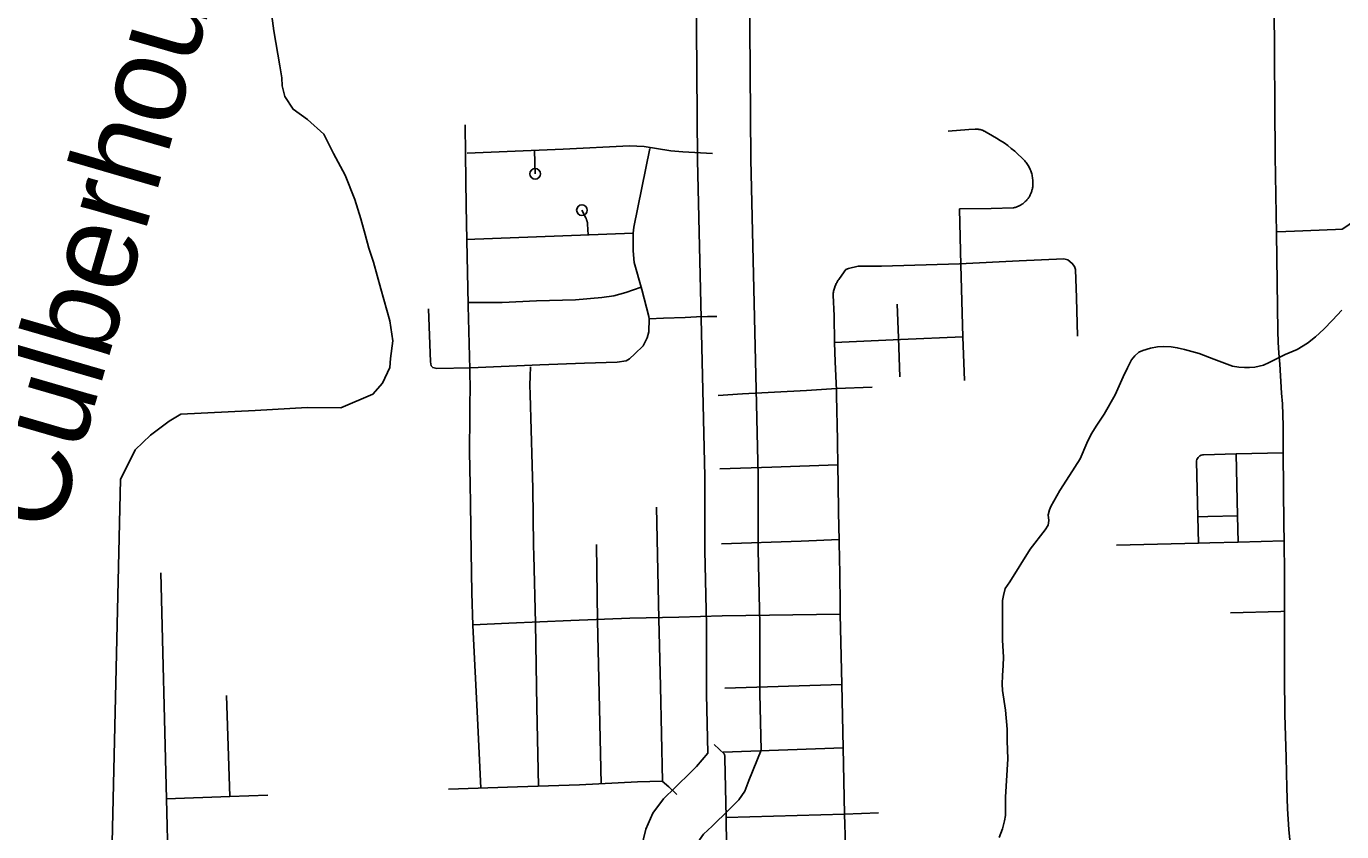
# Model space of a CAD drawing. Extents: x 309348 to 309445, y 336383 to 336484.
# Drawn here: x 309348.279 to 309349.513, y 336400.809 to 336401.564 of the extents above; entities that cross this region are included whole.
import ezdxf

# ---------------------------------------------------------------- set-up
doc = ezdxf.new("R2010")
doc.units = 0
doc.layers.add('R_Annotation', color=7, linetype='Continuous')

msp = doc.modelspace()

# ---------------------------------------------------------------- linework, layer by layer
at = {"layer": 'R_Annotation'}
for points in [[(309348.9004, 336402.0724), (309348.9007, 336402.03), (309348.9072, 336401.6455), (309348.9086, 336401.4386), (309348.9156, 336401.1419), (309348.9156, 336401.0724), (309348.9171, 336401.0028), (309348.9171, 336400.9377), (309348.9184, 336400.8825)], [(309348.9683, 336400.8852), (309348.9671, 336400.9383), (309348.9672, 336401.0034), (309348.9656, 336401.073), (309348.9656, 336401.1425), (309348.9586, 336401.4393), (309348.9572, 336401.6461), (309348.9507, 336402.0306), (309348.9504, 336402.0727)], [(309349.4519, 336401.3699), (309349.4507, 336401.4424), (309349.4496, 336401.5842), (309349.4479, 336401.6818), (309349.4472, 336401.7383), (309349.4474, 336401.7684)], [(309348.5067, 336401.5951), (309348.5113, 336401.56), (309348.517, 336401.5271), (309348.5187, 336401.5158), (309348.5192, 336401.5084), (309348.5215, 336401.4982), (309348.5294, 336401.4863), (309348.543, 336401.4766), (309348.5583, 336401.463), (309348.5674, 336401.4449), (309348.5782, 336401.4245), (309348.5873, 336401.4018), (309348.5929, 336401.3836), (309348.5969, 336401.3689), (309348.6003, 336401.3559), (309348.6048, 336401.3428), (309348.6116, 336401.3179), (309348.6201, 336401.2878), (309348.623, 336401.2691), (309348.6207, 336401.2527), (309348.6201, 336401.2441), (309348.6133, 336401.2294), (309348.6043, 336401.2192), (309348.5742, 336401.2062), (309348.5425, 336401.2067), (309348.4937, 336401.2039), (309348.424, 336401.2005), (309348.4132, 336401.1937), (309348.3956, 336401.1806), (309348.3811, 336401.1669), (309348.3676, 336401.139), (309348.3568, 336400.6761)], [(309348.6911, 336401.4441), (309348.6907, 336401.4716)], [(309349.1544, 336401.3929), (309349.1843, 336401.3933), (309349.2052, 336401.3939), (309349.206, 336401.3941), (309349.2068, 336401.3943), (309349.2075, 336401.3945), (309349.2082, 336401.3948), (309349.209, 336401.3951), (309349.2097, 336401.3954), (309349.2104, 336401.3957), (309349.2111, 336401.396), (309349.2118, 336401.3964), (309349.2125, 336401.3968), (309349.2131, 336401.3972), (309349.2138, 336401.3977), (309349.2144, 336401.3981), (309349.215, 336401.3986), (309349.2156, 336401.3991), (309349.2162, 336401.3997), (309349.2167, 336401.4002), (309349.2173, 336401.4008), (309349.2178, 336401.4014), (309349.2183, 336401.402), (309349.2188, 336401.4026), (309349.2192, 336401.4032), (309349.2197, 336401.4039), (309349.2201, 336401.4045), (309349.2205, 336401.4052), (309349.2208, 336401.4059), (309349.2212, 336401.4066), (309349.2215, 336401.4073), (309349.2218, 336401.408), (309349.2221, 336401.4088), (309349.2223, 336401.4095), (309349.2225, 336401.4103), (309349.2227, 336401.411), (309349.2229, 336401.4118), (309349.223, 336401.4126), (309349.2232, 336401.4137), (309349.2233, 336401.4147), (309349.2233, 336401.4158), (309349.2234, 336401.4169), (309349.2234, 336401.418), (309349.2233, 336401.4191), (309349.2232, 336401.4202), (309349.2231, 336401.4213), (309349.223, 336401.4224), (309349.2228, 336401.4234), (309349.2226, 336401.4245), (309349.2223, 336401.4256), (309349.222, 336401.4266), (309349.2217, 336401.4276), (309349.2213, 336401.4287), (309349.2209, 336401.4297), (309349.2204, 336401.4307), (309349.2199, 336401.4317), (309349.2194, 336401.4326), (309349.2189, 336401.4336), (309349.2183, 336401.4345), (309349.2177, 336401.4354), (309349.2171, 336401.4363), (309349.2164, 336401.4371), (309349.2157, 336401.438), (309349.215, 336401.4388), (309349.2142, 336401.4396), (309349.2134, 336401.4403), (309349.2126, 336401.4411), (309349.2096, 336401.444), (309349.2064, 336401.4469), (309349.2031, 336401.4496), (309349.1998, 336401.4522), (309349.1964, 336401.4547), (309349.1928, 336401.4571), (309349.1892, 336401.4593), (309349.1856, 336401.4614), (309349.1795, 336401.4648), (309349.179, 336401.4651), (309349.1786, 336401.4654), (309349.1781, 336401.4657), (309349.1776, 336401.4659), (309349.1771, 336401.4661), (309349.1766, 336401.4664), (309349.1761, 336401.4666), (309349.1756, 336401.4667), (309349.1751, 336401.4669), (309349.1746, 336401.467), (309349.1741, 336401.4672), (309349.1735, 336401.4673), (309349.173, 336401.4674), (309349.1725, 336401.4674), (309349.1719, 336401.4675), (309349.1714, 336401.4675), (309349.1709, 336401.4676), (309349.1703, 336401.4676), (309349.1698, 336401.4675), (309349.1692, 336401.4675), (309349.1632, 336401.4673), (309349.1438, 336401.4656)], [(309349.635, 336401.4594), (309349.5895, 336401.4273), (309349.562, 336401.4076), (309349.5169, 336401.376), (309349.5135, 336401.374), (309349.5073, 336401.3734), (309349.4687, 336401.372), (309349.4525, 336401.3714)], [(309348.6925, 336401.4451), (309348.7828, 336401.4488), (309348.845, 336401.4519), (309348.8587, 336401.4513), (309348.8837, 336401.4473), (309348.8949, 336401.4463), (309348.9229, 336401.4448)], [(309348.7557, 336401.4477), (309348.7564, 336401.4258)], [(309348.8484, 336401.3691), (309348.8484, 336401.3701), (309348.8491, 336401.3757), (309348.8639, 336401.4496)], [(309348.6923, 336401.3635), (309348.6916, 336401.3957), (309348.6911, 336401.4441)], [(309348.8061, 336401.3684), (309348.8055, 336401.3786), (309348.8055, 336401.3791), (309348.8054, 336401.3796), (309348.8054, 336401.3801), (309348.8053, 336401.3806), (309348.8052, 336401.3811), (309348.805, 336401.3816), (309348.8049, 336401.3821), (309348.8047, 336401.3826), (309348.8046, 336401.3831), (309348.8044, 336401.3836), (309348.8042, 336401.3841), (309348.8039, 336401.3845), (309348.8003, 336401.3917)], [(309349.1557, 336401.3402), (309349.1544, 336401.3929)], [(309348.8484, 336401.37), (309348.6918, 336401.3641)], [(309348.6936, 336401.302), (309348.6936, 336401.3031), (309348.6923, 336401.3635)], [(309348.8564, 336401.3172), (309348.8494, 336401.3426), (309348.8483, 336401.3535), (309348.8484, 336401.3691)], [(309349.4652, 336400.7914), (309349.4635, 336400.8108), (309349.4623, 336400.8303), (309349.4616, 336400.8498), (309349.4609, 336400.8786), (309349.4597, 336400.9184), (309349.4594, 336400.9548), (309349.4594, 336401.0155), (309349.4595, 336401.0503), (309349.459, 336401.0815), (309349.4588, 336401.0969), (309349.4582, 336401.1642), (309349.458, 336401.1895), (309349.4578, 336401.1998), (309349.4574, 336401.21), (309349.4567, 336401.2202), (309349.4551, 336401.2472), (309349.454, 336401.2575), (309349.4533, 336401.2679), (309349.453, 336401.2783), (309349.4519, 336401.3699)], [(309349.0419, 336401.3275), (309349.048, 336401.3359), (309349.0505, 336401.337), (309349.0594, 336401.339), (309349.0812, 336401.3393), (309349.1546, 336401.3414), (309349.2106, 336401.3443), (309349.2524, 336401.346), (309349.2561, 336401.345), (309349.2603, 336401.3417), (309349.2625, 336401.3388), (309349.2632, 336401.3359), (309349.2643, 336401.3096), (309349.2651, 336401.2736)], [(309349.1575, 336401.2729), (309349.1557, 336401.3402)], [(309349.0373, 336401.2677), (309349.0368, 336401.2926), (309349.0359, 336401.312), (309349.036, 336401.313), (309349.0361, 336401.3139), (309349.0363, 336401.3148), (309349.0364, 336401.3157), (309349.0366, 336401.3166), (309349.0369, 336401.3176), (309349.0371, 336401.3185), (309349.0374, 336401.3193), (309349.0377, 336401.3202), (309349.0381, 336401.3211), (309349.0384, 336401.3219), (309349.0388, 336401.3228), (309349.0393, 336401.3236), (309349.0397, 336401.3244), (309349.0402, 336401.3252), (309349.0407, 336401.326), (309349.0413, 336401.3268), (309349.0419, 336401.3275)], [(309348.8558, 336401.3193), (309348.8414, 336401.3143), (309348.8303, 336401.3114), (309348.8189, 336401.3097), (309348.7942, 336401.3077), (309348.7576, 336401.3066), (309348.7255, 336401.3052), (309348.6938, 336401.305)], [(309348.8564, 336401.3172), (309348.8631, 336401.2921)], [(309348.6957, 336401.2439), (309348.6642, 336401.2431), (309348.6603, 336401.244), (309348.659, 336401.2456), (309348.6582, 336401.2494), (309348.6563, 336401.2992)], [(309348.6953, 336401.2424), (309348.6936, 336401.302)], [(309349.0961, 336401.3034), (309349.0973, 336401.2718), (309349.0984, 336401.2353)], [(309349.4316, 336401.2445), (309349.4396, 336401.2463), (309349.4451, 336401.2489), (309349.4599, 336401.2562), (309349.4713, 336401.2611), (309349.4809, 336401.2668), (309349.4883, 336401.2729), (309349.4963, 336401.2801), (309349.5043, 336401.2886), (309349.5132, 336401.2978)], [(309348.8631, 336401.2921), (309348.8634, 336401.2898), (309348.8632, 336401.2775), (309348.8615, 336401.2719), (309348.8576, 336401.2644), (309348.8499, 336401.257), (309348.8448, 336401.2522), (309348.8418, 336401.2503), (309348.8334, 336401.2491), (309348.8027, 336401.2483), (309348.7609, 336401.2466), (309348.6957, 336401.2439)], [(309348.8634, 336401.2898), (309348.8769, 336401.2903), (309348.897, 336401.2909), (309348.9077, 336401.2916), (309348.9181, 336401.2918), (309348.9268, 336401.292)], [(309349.0993, 336401.2704), (309349.1575, 336401.2729)], [(309349.1591, 336401.2318), (309349.1575, 336401.2729)], [(309349.0373, 336401.2677), (309349.0993, 336401.2704)], [(309349.039, 336401.2229), (309349.038, 336401.2495), (309349.0373, 336401.2677)], [(309349.1916, 336400.8033), (309349.1947, 336400.8116), (309349.1967, 336400.8189), (309349.1975, 336400.8241), (309349.1975, 336400.8412), (309349.1999, 336400.8771), (309349.1993, 336400.8939), (309349.1991, 336400.9049), (309349.1975, 336400.9228), (309349.1947, 336400.9412), (309349.1944, 336400.9472), (309349.1947, 336400.9552), (309349.1954, 336400.9648), (309349.1957, 336400.9726), (309349.1949, 336400.9885), (309349.1947, 336401.0085), (309349.1947, 336401.0222), (309349.1949, 336401.0256), (309349.1957, 336401.0303), (309349.1973, 336401.037), (309349.2017, 336401.043), (309349.2209, 336401.0739), (309349.2349, 336401.0918), (309349.2377, 336401.0962), (309349.2383, 336401.1006), (309349.2377, 336401.1058), (309349.239, 336401.1105), (309349.2403, 336401.1139), (309349.2486, 336401.1287), (309349.2577, 336401.1427), (309349.2678, 336401.1585), (309349.2741, 336401.1731), (309349.278, 336401.1816), (309349.2832, 336401.19), (309349.2902, 336401.2003), (309349.3005, 336401.2185), (309349.3081, 336401.2354), (309349.312, 336401.2437), (309349.3158, 336401.2512), (309349.319, 336401.2551), (309349.3226, 336401.2585), (309349.3265, 336401.2601), (309349.3338, 336401.2621), (309349.3402, 336401.2634), (309349.3457, 336401.2637), (309349.3532, 336401.2634), (309349.3587, 336401.2627), (309349.3657, 336401.2611), (309349.3792, 336401.2572), (309349.3932, 336401.2518), (309349.4106, 336401.2453), (309349.4165, 336401.2445), (309349.4217, 336401.244), (309349.4266, 336401.244), (309349.4316, 336401.2445)], [(309348.6956, 336401.1339), (309348.6949, 336401.1653), (309348.6951, 336401.1986), (309348.6953, 336401.2125), (309348.6956, 336401.222), (309348.6953, 336401.2424)], [(309348.7535, 336401.1524), (309348.7516, 336401.2188), (309348.7515, 336401.2275), (309348.7517, 336401.2361), (309348.7521, 336401.2448)], [(309349.039, 336401.2243), (309349.0111, 336401.2226), (309348.9509, 336401.2193), (309348.9282, 336401.218)], [(309349.039, 336401.2243), (309349.0727, 336401.2257)], [(309349.0404, 336401.1503), (309349.0399, 336401.1761), (309349.0392, 336401.2178), (309349.039, 336401.2229)], [(309349.4582, 336401.1642), (309349.4139, 336401.1631), (309349.3834, 336401.1623), (309349.3823, 336401.1622), (309349.3812, 336401.1618), (309349.3801, 336401.1613), (309349.3792, 336401.1606), (309349.3783, 336401.1598), (309349.3777, 336401.1588), (309349.3772, 336401.1577), (309349.3769, 336401.1565), (309349.3769, 336401.1559), (309349.3782, 336401.104), (309349.3788, 336401.0794)], [(309349.4139, 336401.1631), (309349.4154, 336401.105), (309349.416, 336401.0803)], [(309348.7549, 336401.0768), (309348.7541, 336401.1314), (309348.7538, 336401.1411), (309348.7535, 336401.1524)], [(309348.9296, 336401.1492), (309348.9784, 336401.1507), (309349.0399, 336401.1529)], [(309349.0415, 336401.0819), (309349.0411, 336401.1083), (309349.0407, 336401.1356), (309349.0404, 336401.1503)], [(309348.6962, 336401.0928), (309348.6959, 336401.1176), (309348.6956, 336401.1339)], [(309348.8726, 336401.0083), (309348.8704, 336401.1131)], [(309349.4154, 336401.105), (309349.3873, 336401.1043), (309349.3782, 336401.104)], [(309348.6981, 336401.0023), (309348.697, 336401.0329), (309348.6965, 336401.0712), (309348.6962, 336401.0928)], [(309348.7566, 336401.0042), (309348.7551, 336401.068), (309348.7549, 336401.0768)], [(309348.8149, 336401.0065), (309348.8139, 336401.078)], [(309349.0415, 336401.0828), (309349.0061, 336401.0812), (309348.9311, 336401.0788)], [(309349.0426, 336401.0129), (309349.0425, 336401.0214), (309349.0423, 336401.051), (309349.0416, 336401.0797), (309349.0415, 336401.0819)], [(309349.459, 336401.0815), (309349.416, 336401.0803), (309349.3892, 336401.0797), (309349.3788, 336401.0794), (309349.3017, 336401.0774)], [(309348.4105, 336400.8396), (309348.4052, 336401.0516)], [(309349.4594, 336401.0155), (309349.456, 336401.0154), (309349.4087, 336401.0139)], [(309348.6981, 336401.0029), (309348.7317, 336401.0042), (309348.7898, 336401.0067), (309348.8451, 336401.0089), (309348.8913, 336401.0099), (309348.9319, 336401.0111)], [(309348.7023, 336400.9151), (309348.6981, 336401.0023)], [(309348.7581, 336400.9255), (309348.7566, 336401.0042)], [(309348.8167, 336400.9246), (309348.8149, 336401.0065)], [(309348.8739, 336400.9451), (309348.8726, 336401.0083)], [(309348.9319, 336401.0111), (309349.0426, 336401.0129)], [(309349.044, 336400.9469), (309349.0426, 336401.0129)], [(309348.8758, 336400.8562), (309348.8739, 336400.9451)], [(309348.9344, 336400.9435), (309349.044, 336400.9469)], [(309349.0454, 336400.8873), (309349.044, 336400.9469)], [(309348.4701, 336400.8418), (309348.4669, 336400.9364)], [(309348.7054, 336400.8497), (309348.7023, 336400.9151)], [(309348.7595, 336400.8514), (309348.7581, 336400.9255)], [(309348.8183, 336400.8538), (309348.8167, 336400.9246)], [(309348.9337, 336400.8818), (309348.9242, 336400.8906)], [(309348.9184, 336400.8825), (309348.9079, 336400.8698), (309348.9032, 336400.8652), (309348.8877, 336400.8502), (309348.8767, 336400.8397), (309348.8667, 336400.8262), (309348.8604, 336400.8112), (309348.8559, 336400.7929), (309348.8572, 336400.7658)], [(309348.9072, 336400.7683), (309348.9062, 336400.7881), (309348.908, 336400.7954), (309348.9105, 336400.8012), (309348.9143, 336400.8065), (309348.9224, 336400.8141), (309348.938, 336400.8293), (309348.9475, 336400.8386), (309348.9532, 336400.8467), (309348.9568, 336400.8567), (309348.9683, 336400.8852)], [(309348.9329, 336400.8834), (309349.0454, 336400.8873)], [(309348.9355, 336400.8221), (309348.9344, 336400.8778), (309348.9344, 336400.8788), (309348.9344, 336400.879), (309348.9344, 336400.8792), (309348.9344, 336400.8794), (309348.9344, 336400.8796), (309348.9344, 336400.8798), (309348.9343, 336400.88), (309348.9343, 336400.8802), (309348.9343, 336400.8803), (309348.9342, 336400.8805), (309348.9341, 336400.8807), (309348.9341, 336400.8809), (309348.934, 336400.8811), (309348.9337, 336400.8818)], [(309349.0467, 336400.8253), (309349.0454, 336400.8873)], [(309348.6752, 336400.8488), (309348.7399, 336400.8508), (309348.7979, 336400.8527), (309348.8525, 336400.8557), (309348.8755, 336400.8562), (309348.8819, 336400.8508), (309348.8894, 336400.8436)], [(309348.4701, 336400.8418), (309348.4105, 336400.8396)], [(309348.5057, 336400.8431), (309348.4701, 336400.8418)], [(309348.4121, 336400.7751), (309348.4105, 336400.8396)], [(309348.9355, 336400.8221), (309349.0467, 336400.8253)], [(309348.936, 336400.7955), (309348.9355, 336400.8221)], [(309349.0467, 336400.8253), (309349.0785, 336400.8264)], [(309349.0484, 336400.7666), (309349.0467, 336400.8253)]]:
    msp.add_lwpolyline(points, dxfattribs=at)
for centre in [(309348.7564, 336401.4258), (309348.8003, 336401.3917)]:
    msp.add_circle(centre, 0.005, dxfattribs=at)

# ---------------------------------------------------------------- texts
msp.add_text('Culberhouse', height=0.084508, rotation=73.8116, dxfattribs=at).set_placement((309348.3078, 336401.086))

doc.saveas('drawing.dxf')
